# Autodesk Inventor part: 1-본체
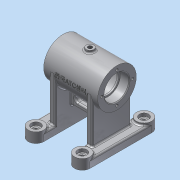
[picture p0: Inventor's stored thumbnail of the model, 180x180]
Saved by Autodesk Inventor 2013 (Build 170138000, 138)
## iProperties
Created: 2015-11
Part Number: 1-본체
Material: 알루미늄 6061
Document SubType Name: Modeling
Designer: ST1
Density: 2.71 g/cm^3
Mass: 357.406 g
Surface Area: 463.119 cm^2
Volume: 131.884 cm^3
Author: ST1
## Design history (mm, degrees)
sketch "스케치1"
  geometry: L1 (0, 0)-(70, 0); L2 (0, 16)-(12, 16); L3 (70, 16)-(58, 16); L4 (12, 16)-(12, 14); L5 (58, 16)-(58, 14); L6 (12, 14)-(14, 14); L7 (58, 14)-(56, 14); L8 (14, 14)-(14, 21); L9 (14, 21)-(56, 21); L10 (56, 21)-(56, 14); L11 (0, 16)-(0, 25); L12 (0, 25)-(70, 25); L13 (70, 25)-(70, 16)
  constraints: 26 end point, 6 perpendicular, 3 collinear, 3 parallel, 2 horizontal, 2 horizontal alignment, 2 vertical alignment, 1 vertical
  dimensions: "d0" = 70 distance of L1.start L1.end; "d1" = 32 diameter of L2 L1; "d2" = 12.00042 distance of L2.start L2.end; "d3" = 28 diameter of L4.end L1; "d4" = 42 diameter of L9 L1; "d5" = 42 distance of L8.end L9.end; "d6" = 50 diameter of L11.end L1
revolve "회전1" sketch "스케치1" stored, may be unused: angle "d7" = 90 deg
sketch "스케치2"
  geometry: C1 r 16 at (0, 0) reference; C2 r 25 at (0, 0) reference; A1 r 20 centre (0, 0) between (0, 20) and (20, 0); 2 further points
  constraints: 4 point on circle, 2 horizontal alignment, 2 vertical alignment, 1 centre point, 1 coincident
  dimensions: "d8" = 40 diameter of A1
hole "구멍1" sketch "스케치2" at (0, 20), (20, 0), (-20, 0), (0, -20) diameter "d10" = 3.242; stored, may be unused: countersink angle "d14" = 90 deg, drill point angle "d16" = 118 deg; dims "d11" = 8, "d12" = 4, "d13" = 2, "d15" = 10
node "작업 평면1"
node "작업 평면3"
  node "작업 평면2"
sketch "스케치3"
  geometry: C1 r 5 at (0, 0); 1 further point
  constraints: 1 centre point, 1 horizontal alignment
  dimensions: "d18" = 35 distance of C1.centre point (-35, 0); "d19" = 10 diameter of C1
extrude "돌출1" join sketch "스케치3" stored distance "d20" = 3; taper "d21" = 0 deg
sketch "스케치4"
  geometry: C1 r 5 at (0, 0) reference; 2 further points
  constraints: 1 coincident
hole "구멍2" sketch "스케치4" at (0, 0) diameter "d22" = 5.188; stored, may be unused: countersink angle "d26" = 90 deg, drill point angle "d28" = 118 deg; dims "d23" = 8, "d24" = 4, "d25" = 2, "d27" = 10
sketch "스케치5"
  geometry: L1 (0, 0)-(0, 25); L2 (0, 0)-(21.651, 12.5); L3 (21.651, 12.5)-(24.249, 14); L4 (0, 0)-(19.555, 0); A1 r 25 centre (0, 0) between (21.651, 12.5) and (0, 25) reference; 1 further point
  constraints: 8 end point, 2 point on circle, 1 collinear, 1 perpendicular, 1 vertical
  dimensions: "d31" = 28 distance of L3.end point (0, 0); "d44" = 30 deg angle of L4 L2
node "작업 평면4"
sketch "스케치6"
  geometry: C1 r 6 at (0, 0); 1 further point
  constraints: 1 centre point, 1 horizontal alignment
  dimensions: "d32" = 12 diameter of C1; "d34" = 35 distance of point (35, 0) C1.centre
extrude "돌출2" join sketch "스케치6" stored distance "d35" = 10; taper "d36" = 0 deg
sketch "스케치7"
  geometry: C1 r 6 at (0, 0) reference; 2 further points
  constraints: 1 coincident
hole "구멍3" sketch "스케치7" at (0, 0) diameter "d37" = 5.188; stored, may be unused: countersink angle "d41" = 90 deg, drill point angle "d43" = 118 deg; dims "d38" = 8, "d39" = 4, "d40" = 2, "d42" = 10
chamfer "모따기1" distance "d45" = 1; stored, may be unused: second distance "d46" = 2, angle "d47" = 45 deg
fillet "모깎기1" dims "d48" = 3
fillet "모깎기2" dims "d49" = 0.3
node "작업 평면5"
sketch "스케치8"
  geometry: L1 (-5, 40)-(95, 40); L2 (95, 40)-(95, -40); L3 (95, -40)-(-5, -40); L4 (-5, -40)-(-5, 40); L5 (70, -25)-(70, 25) reference; 2 further points
  constraints: 8 end point, 2 parallel, 1 horizontal, 1 horizontal alignment, 1 midpoint, 1 perpendicular
  dimensions: "d51" = 80 distance of L1.end L2.end; "d53" = 100 distance of L1.start L1.end; "d54" = 5 distance of point (-5, 0) point (0, 0)
extrude "돌출3" join sketch "스케치8" distance "d55" = 10; taper "d56" = 0 deg
sketch "스케치9"
  geometry: L1 (95, 40)-(-5, 40) reference; L2 (-5, 40)-(-5, -40) reference; L3 (-5, -40)-(95, -40) reference; L4 (95, -40)-(95, 40) reference; L5 (15, 40)-(15, -40); L6 (75, 40)-(75, -40); 5 further points
  constraints: 8 point on line, 4 end point, 2 perpendicular
  dimensions: "d84" = 20 distance between parallel lines of L2 L5; "d85" = 20 distance between parallel lines of L4 L6
extrude "돌출4" cut sketch "스케치9" distance "d59" = 10; taper "d60" = 0 deg
sketch "스케치15"
  geometry: L1 (75, -40)-(75, 40) reference; L2 (75, 40)-(-5, 40) reference; L3 (-5, 40)-(-5, -40) reference; L4 (-5, -40)-(75, -40) reference; L5 (15, 40)-(15, -40); L6 (55, 40)-(55, -40); 1 further point
  constraints: 4 end point, 4 point on line, 2 perpendicular
  dimensions: "d86" = 20 distance between parallel lines of L3 L5; "d87" = 20 distance between parallel lines of L1 L6
extrude "돌출9" cut sketch "스케치15" distance "d88" = 100; taper "d89" = 0 deg
sketch "스케치16"
  geometry: L1 (15, 40)-(-5, 40) reference; L2 (-5, -40)-(15, -40) reference; L3 (75, 40)-(75, -40) reference; L4 (55, -40)-(55, 40) reference; L5 (55, 40)-(75, 40) reference; L6 (75, 40)-(75, -40) reference; L7 (75, -40)-(55, -40) reference; 5 further points
  constraints: 4 horizontal alignment, 4 midpoint, 8 other
extrude "돌출10" join sketch "스케치16" distance "d90" = 3; taper "d91" = 0 deg
sketch "스케치17"
  geometry: L1 (5, -40)-(-15, -40) reference; C1 r 10 at (-5, 40) reference; C2 r 10 at (-65, 40) reference; C3 r 10 at (-65, -40) reference; A1 r 10 centre (-5, -40) between (-15, -40) and (5, -40) reference; 1 further point
extrude "돌출11" join sketch "스케치17" distance "d92" = 10; taper "d93" = 0 deg
sketch "스케치18"
  geometry: L1 (10, 80)-(10, 0) reference; L2 (-10, 0)-(-10, 80) reference; L3 (70, 80)-(70, 0) reference; L4 (50, 0)-(50, 80) reference; C1 r 6 at (0, 0); C2 r 6 at (60, 0); C3 r 6 at (60, 80); C4 r 6 at (0, 80); A1 r 10 centre (0, 0) between (-10, 0) and (10, 0) reference; A2 r 10 centre (0, 80) between (10, 80) and (-10, 80) reference; A3 r 10 centre (60, 0) between (50, 0) and (70, 0) reference; A4 r 10 centre (60, 80) between (70, 80) and (50, 80) reference; 1 further point
  constraints: 4 centre point, 4 coincident, 3 equal radius
  dimensions: "d94" = 12 diameter of C4
extrude "돌출12" cut sketch "스케치18" distance "d96" = 4; taper "d97" = 0 deg
sketch "스케치19"
  geometry: L1 (-50, 80)-(-50, 0) reference; L2 (-70, 0)-(-70, 80) reference; C1 r 10 at (0, 0) reference; C2 r 6 at (0, 80) reference; C3 r 3 at (-60, 0); C4 r 3 at (0, 0); C5 r 3 at (0, 80); C6 r 3 at (-60, 80); A1 r 10 centre (-60, 0) between (-70, 0) and (-50, 0) reference; A2 r 10 centre (-60, 80) between (-50, 80) and (-70, 80) reference; 1 further point
  constraints: 4 centre point, 4 coincident, 3 equal radius
  dimensions: "d98" = 6 diameter of C3
extrude "돌출13" cut sketch "스케치19" distance "d100" = 100; taper "d101" = 0 deg
fillet "모깎기4" dims "d102" = 0.3
chamfer "모따기3" distance "d103" = 1; stored, may be unused: second distance "d104" = 2, angle "d105" = 45 deg
sketch "스케치20"
  geometry: L1 (15, -40)-(15, 40) reference; L2 (15, 25)-(7, 25); L3 (7, 25)-(7, -25); L4 (7, -25)-(15, -25); 2 further points
  constraints: 6 end point, 3 perpendicular, 2 point on line, 1 horizontal alignment, 1 midpoint
  dimensions: "d106" = 8 distance between parallel lines of L3 L1; "d107" = 50 distance of L2.end L3.end
extrude "돌출14" join sketch "스케치20" stored distance "d108" = 100; taper "d109" = 0 deg
node "작업 평면6"
node "작업 평면7"
sketch "스케치21"
  geometry: L1 (0, 58)-(8, 58) reference; L2 (8, 0)-(8, 58) reference; L3 (0, 0)-(8, 0) reference; L4 (0, 0)-(0, 58) reference; L5 (-7, 33)-(63, 33) reference; L6 (48, 58)-(56, 58) reference; L7 (56, 0)-(56, 58) reference; L8 (48, 0)-(56, 0) reference; L9 (48, 0)-(48, 58) reference; L10 (8, 13)-(48, 13); L11 (8, 13)-(8, 33); L12 (8, 33)-(48, 33); L13 (48, 33)-(48, 13); 1 further point
  constraints: 8 end point, 6 point on line, 1 collinear, 1 perpendicular
  dimensions: "d110" = 20 distance between parallel lines of L10 L5
extrude "돌출15" join sketch "스케치21" stored distance "d111" = 8; taper "d112" = 0 deg
sketch "스케치22"
  geometry: L1 (0, 0)-(-40, 0) reference; L2 (0, 4)-(0, 0) reference; L3 (-40, 4)-(0, 4) reference; L4 (-40, 0)-(-40, 4) reference; 1 further point
extrude "돌출16" join sketch "스케치22" stored distance "d113" = 8; taper "d114" = 0 deg
sketch "스케치23"
  geometry: L1 (8, 33.322)-(48, 33.322) reference; L2 (61, -10)-(55, -10) reference; L3 (16.5, 26.5)-(39.5, 26.5); L4 (16.5, 19.5)-(39.5, 19.5); A1 r 3.5 centre (16.5, 23) between (16.5, 26.5) and (16.5, 19.5); A2 r 3.5 centre (39.5, 23) between (39.5, 19.5) and (39.5, 26.5); 2 further points
  constraints: 4 end point, 4 point on circle, 4 tangent, 2 centre point, 1 equal radius, 1 horizontal alignment, 1 midpoint
  dimensions: "d115" = 33 distance from line of A2.centre L2; "d116" = 23 distance of A2.centre A1.centre; "d117" = 7 diameter of A2; "d119" = 11.5 horizontal distance of point (28, 33.322) A1.centre
extrude "돌출17" cut sketch "스케치23" stored distance "d120" = 8; taper "d121" = 0 deg
fillet "모깎기5" dims "d122" = 2
fillet "모깎기6" dims "d123" = 2
fillet "모깎기7" dims "d124" = 2
fillet "모깎기8" dims "d125" = 2
fillet "모깎기9" dims "d126" = 2
node "작업 평면8"
sketch "스케치24"
  geometry: L1 (-35, 25)-(35, 25) reference; 2 further points
  constraints: 1 horizontal alignment, 1 other
  dimensions: "d128" = 35 distance of point (0, 0) point (-35, 0)
feature "엠보싱1" sketch "스케치24" dims "d129" = 0.5, "d130" = 0
fillet "모깎기11" dims "d131" = 2
fillet "모깎기12" dims "d132" = 2
node "솔리드1"
mirror "대칭1"
mirror "대칭2"
node "투영된 루프8"
node "투영된 루프9"
node "투영된 루프10"
node "투영된 루프11"
node "투영된 루프12"
node "투영된 루프13"
node "투영된 루프14"
node "투영된 루프15"
node "투영된 루프16"
node "투영된 루프17"
other parameters: "d17" = 3, "d50" = -68
